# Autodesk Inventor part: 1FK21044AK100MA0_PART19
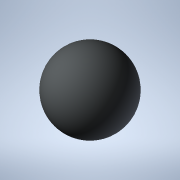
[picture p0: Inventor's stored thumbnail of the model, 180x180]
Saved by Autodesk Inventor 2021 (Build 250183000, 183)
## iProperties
Created: 2025-04
Part Number: 1FK21044AK100MA0_PART19
Material: Generic
Catalog Web Link: www.3dfindit.com
Description: -Servo synchronous motor
Document SubType Name: Modeling
Designer: psAdmin
Mass: 0.137258 g
Surface Area: 1.2868 cm^2
Volume: 0.137258 cm^3
Density: 1 g/cm^3
Appearance: PSOLRGB-212-217-219
Category: PARTsolutions
Title: 1FK21044AK100MA0_PART19
Author: Cadenas PARTsolutions
Comments: Servo synchronous motor
Sending System: PARTsolutions
Preprocessor: ST-DEVELOPER v19.3
PSOL_IDENT_0: {$CADENAS_DATA/23d-libs/siemens_ag/_cat_/5e/d8/1fk21044ak100ma0.prj},216 {VTYP=3D},{NB=1FK21044AK100
PSOL_IDENT_1: MA0_PART19},{LINA=1FK21044AK100MA0_PART19},{NN=1FK21044AK100MA0_PART19},{NOPRJ=TRUE},{DATE=19.08.202
PSOL_IDENT_2: 5 14:00:41},{GEOMDATE=30.07.2025 02:00:53},{VERSION=},{LINEID=10},{WBVAR=},{WBNUMERIC=}  {NB=1FK2104
PSOL_IDENT_3: 4AK100MA0_PART19},{LINA=1FK21044AK100MA0_PART19},{KT=DUMMY},{PREVIEW=../../../_pool_/cb/72/p_d211_xx
PSOL_IDENT_4: _00434j.png},{DESCSHORT=SIMOTICS S-1FK2 HD, SINAMICS S210 3AC 400V-480V, 0.95 Nm, 6000 rpm},{DESCLON
PSOL_IDENT_5: G=SIMOTICS S-1FK2 HD servo motor M0=1.27 Nm; PN = 0.6 kW at nN=6000 rpm (380-480 V); PN = 0.4 kW at
PSOL_IDENT_6: nN=3000 rpm (200-240 V); with holding brake; degree of protection IP64; cylindrical shaft D19x40mm;
PSOL_IDENT_7: absolute encoder 22-bit + 12-bit multiturn (encoder AM22DQC); with OCC interface; plug size M17, rot
PSOL_IDENT_8: atable; SIMOTICS S-1FK2 servomotorfor a wide range of uses in industrial environments. SIMOTICS S‑1F
PSOL_IDENT_9: K2 servomotors are compact synchronous motors with a high dynamic performance that set themselves ap
PSOL_IDENT_10: art as a result of their high power density, degree of protection and overload capability. The motor
PSOL_IDENT_11: s are available in two variants: as High Dynamic variant (highest dynamic performance as a result of
PSOL_IDENT_12: the low intrinsic moment of inertia for applications demanding a high dynamic performance with low
PSOL_IDENT_13: moved masses) - and as Compact variant (precise and stable closed-loop control for medium up to larg
PSOL_IDENT_14: e moved masses as a result of a medium intrinsic moment of inertia). SIMOTICSS‑1FK2 servomotors full
PSOL_IDENT_15: y exploit their strengths in a system with the SINAMICSS210 frequency converter and simple connectio
PSOL_IDENT_16: n using the one cable connection (OCC). Advantages include the short control and positioning times,
PSOL_IDENT_17: fast and precise correction of disturbing quantities as well as stable control with a high dynamic p
PSOL_IDENT_18: erformance. The servo motors can be configured to address a wide range of requirements. For example
PSOL_IDENT_19: with and without holding brake, IP64 or IP65 degree of protection, singleturn or multiturn absolute
PSOL_IDENT_20: encoders - to name just a few. Further, the servomotors are available in different shaft heights ext
PSOL_IDENT_21: ending from 20 to 100. A shaft sealing ring is available to achieve an IP65 degree of protection and
PSOL_IDENT_22: for subsequent mounting at the motor or as spare part. SIMOTICS - the optimum motor for each and ev
PSOL_IDENT_23: ery motion control application.},{INTNO=804766910005},{SUPPLIERALTNO=1FK2104-4AK10-0MA0},{MANUID=1FK
PSOL_IDENT_24: 21044AK100MA0},{MANUNAME=Siemens},{MANUTYPEDESC=Synchronous motor 1FK2-HD 1,27 Nm},{AAU732=SIMOTICS}
PSOL_IDENT_25: ,{AAO057=S-1FK2},{AAU734=SIMOTICS S-1FK2 HD servo motor M0=1.27 Nm; PN = 0.6 kW at nN=6000 rpm (380-
PSOL_IDENT_26: 480 V); PN = 0.4 kW at nN=3000 rpm (200-240 V); with holding brake; degree of protection IP64; cylin
PSOL_IDENT_27: drical shaft D19x40mm; absolute encoder 22-bit + 12-bit multiturn (encoder AM22DQC); with OCC interf
PSOL_IDENT_28: ace; plug size M17, rotatable;},{AAW338=Synchronous motor 1FK2-HD 1,27 Nm},{AAO742=SIMOTICS},{AAO663=
PSOL_IDENT_29: 4042948691076},{NOCUPEROU=1},{PRICEQUANTITY=1},{QUANTITYMIN=1},{QUANTITYINT=1},{CTN=85015100},{COO=D
PSOL_IDENT_30: E},{AAO676=1FK2104-4AK10-0MA0},{AAO677=Siemens AG},{ORDERUNIT=C62},{CONTENTUNIT=C62}
NB: 1FK21044AK100MA0_PART19
NT: Servo synchronous motor
NBSYN: $MANUID._PART19
LINA: 1FK21044AK100MA0_PART19
CATALOG: SIEMENS
PREVIEW: ../../../_pool_/cb/72/p_d211_xx_00434j.png
DESCSHORT: SIMOTICS S-1FK2 HD, SINAMICS S210 3AC 400V-480V, 0.95 Nm, 6000 rpm
DESCLONG: SIMOTICS S-1FK2 HD servo motor M0=1.27 Nm; PN = 0.6 kW at nN=6000 rpm (380-480 V); PN = 0.4 kW at nN=3000 rpm (200-240 V); with holding brake; degree of protect
INTNO: 804766910005
SUPPLIERALTNO: 1FK2104-4AK10-0MA0
MANUID: 1FK21044AK100MA0
MANUNAME: Siemens
MANUTYPEDESC: Synchronous motor 1FK2-HD 1,27 Nm
AAU732: SIMOTICS
AAO057: S-1FK2
AAU734: SIMOTICS S-1FK2 HD servo motor M0=1.27 Nm; PN = 0.6 kW at nN=6000 rpm (380-480 V); PN = 0.4 kW at nN=3000 rpm (200-240 V); with holding brake; degree of protect
AAW338: Synchronous motor 1FK2-HD 1,27 Nm
AAO742: SIMOTICS
AAO663: 4042948691076.0
NOCUPEROU: 1
PRICEQUANTITY: 1
QUANTITYMIN: 1
QUANTITYINT: 1
CTN: 85015100
COO: DE
ARTICLENO: 1FK21044AK100MA0_PART19
BOMINFO: 1FK21044AK100MA0_PART19
CREATOR: CADENAS GmbH
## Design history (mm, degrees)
feature "2025_04_17_15_35_41_0968"
body "Solid1"
